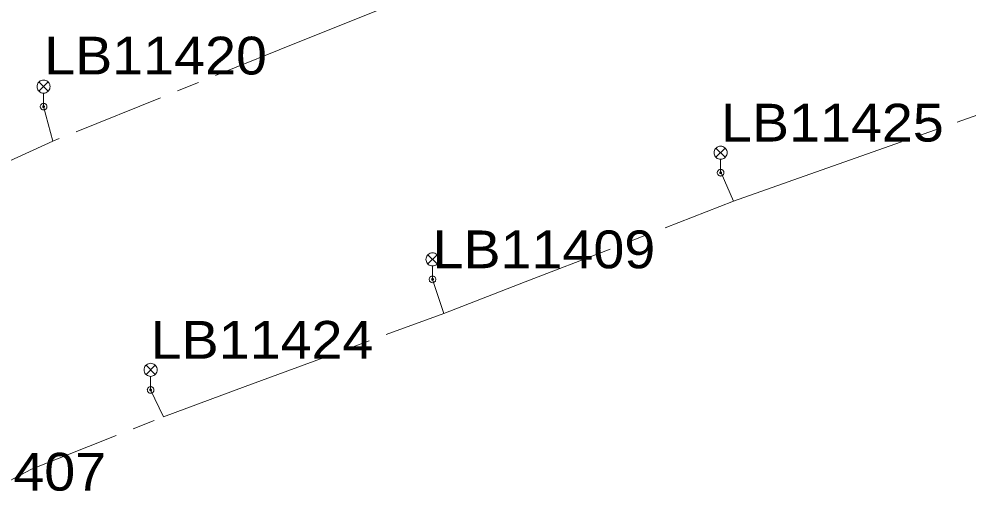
# Model space of a CAD drawing. Extents: x -688049 to -687261, y -973611 to -973038.
# Drawn here: x -687815.7 to -687761.3, y -973356.2 to -973328.5 of the extents above; entities that cross this region are included whole.
import ezdxf

# ---------------------------------------------------------------- set-up
doc = ezdxf.new("R2010")
doc.units = 0
doc.header["$LTSCALE"] = 0.87
doc.linetypes.add('LONG_DASH_SHORT_DASH', pattern=[9.9, 6, -1.2, 1.5, -1.2])
doc.layers.add('1', color=7, linetype='Continuous', lineweight=13)

msp = doc.modelspace()

# ---------------------------------------------------------------- linework, layer by layer
at = {"layer": '1', "linetype": 'LONG_DASH_SHORT_DASH'}
for p, q in [((-687799.628, -973329.809), (-687813.8, -973335.52)), ((-687774.78, -973338.97), (-687770.067, -973337.301)), ((-687791.38, -973345.4), (-687786.718, -973343.594)), ((-687807.46, -973351.33), (-687802.769, -973349.6))]:
    msp.add_line(p, q, dxfattribs=at)
at = {"layer": '1'}
for p, q in [((-687814.595, -973332.125), (-687814.065, -973332.655)), ((-687814.595, -973332.655), (-687814.065, -973332.125)), ((-687814.33, -973333.54), (-687814.33, -973332.765)), ((-687775.78, -973335.915), (-687775.25, -973336.445)), ((-687775.78, -973336.445), (-687775.25, -973335.915)), ((-687775.515, -973337.33), (-687775.515, -973336.555)), ((-687792.295, -973342.035), (-687791.765, -973342.565)), ((-687792.295, -973342.565), (-687791.765, -973342.035)), ((-687792.03, -973343.45), (-687792.03, -973342.675)), ((-687808.455, -973348.375), (-687807.925, -973348.905)), ((-687808.455, -973348.905), (-687807.925, -973348.375)), ((-687808.19, -973349.79), (-687808.19, -973349.015))]:
    msp.add_line(p, q, dxfattribs=at)
at = {"layer": '1', "linetype": 'LONG_DASH_SHORT_DASH'}
for points in [[(-687795.64, -973326.32), (-687794.99, -973327.94), (-687799.628, -973329.809)], [(-687770.067, -973337.301), (-687758.4, -973333.17), (-687759.19, -973331.11)], [(-687814.33, -973333.54), (-687813.8, -973335.52), (-687818.35, -973337.594)], [(-687786.718, -973343.594), (-687774.78, -973338.97), (-687775.49, -973337.33)], [(-687802.769, -973349.6), (-687791.38, -973345.4), (-687792.03, -973343.45)], [(-687818.494, -973356.165), (-687815.02, -973354.34), (-687807.46, -973351.33), (-687808.19, -973349.79)]]:
    msp.add_lwpolyline(points, dxfattribs=at)
at = {"layer": '1'}
for points in [[(-687813.955, -973332.39), (-687813.961, -973332.325), (-687813.978, -973332.262), (-687814.005, -973332.202), (-687814.043, -973332.149), (-687814.089, -973332.103), (-687814.142, -973332.065), (-687814.202, -973332.038), (-687814.265, -973332.021), (-687814.33, -973332.015), (-687814.395, -973332.021), (-687814.458, -973332.038), (-687814.518, -973332.065), (-687814.571, -973332.103), (-687814.617, -973332.149), (-687814.655, -973332.202), (-687814.682, -973332.262), (-687814.699, -973332.325), (-687814.705, -973332.39), (-687814.699, -973332.455), (-687814.682, -973332.518), (-687814.655, -973332.578), (-687814.617, -973332.631), (-687814.571, -973332.677), (-687814.518, -973332.715), (-687814.458, -973332.742), (-687814.395, -973332.759), (-687814.33, -973332.765), (-687814.265, -973332.759), (-687814.202, -973332.742), (-687814.142, -973332.715), (-687814.089, -973332.677), (-687814.043, -973332.631), (-687814.005, -973332.578), (-687813.978, -973332.518), (-687813.961, -973332.455)], [(-687814.14, -973333.54), (-687814.143, -973333.507), (-687814.151, -973333.475), (-687814.165, -973333.445), (-687814.184, -973333.418), (-687814.208, -973333.394), (-687814.235, -973333.375), (-687814.265, -973333.361), (-687814.297, -973333.353), (-687814.33, -973333.35), (-687814.363, -973333.353), (-687814.395, -973333.361), (-687814.425, -973333.375), (-687814.452, -973333.394), (-687814.476, -973333.418), (-687814.495, -973333.445), (-687814.509, -973333.475), (-687814.517, -973333.507), (-687814.52, -973333.54), (-687814.517, -973333.573), (-687814.509, -973333.605), (-687814.495, -973333.635), (-687814.476, -973333.662), (-687814.452, -973333.686), (-687814.425, -973333.705), (-687814.395, -973333.719), (-687814.363, -973333.727), (-687814.33, -973333.73), (-687814.297, -973333.727), (-687814.265, -973333.719), (-687814.235, -973333.705), (-687814.208, -973333.686), (-687814.184, -973333.662), (-687814.165, -973333.635), (-687814.151, -973333.605), (-687814.143, -973333.573)], [(-687814.28, -973333.54), (-687814.281, -973333.531), (-687814.283, -973333.523), (-687814.287, -973333.515), (-687814.292, -973333.508), (-687814.298, -973333.502), (-687814.305, -973333.497), (-687814.313, -973333.493), (-687814.321, -973333.491), (-687814.33, -973333.49), (-687814.339, -973333.491), (-687814.347, -973333.493), (-687814.355, -973333.497), (-687814.362, -973333.502), (-687814.368, -973333.508), (-687814.373, -973333.515), (-687814.377, -973333.523), (-687814.379, -973333.531), (-687814.38, -973333.54), (-687814.379, -973333.549), (-687814.377, -973333.557), (-687814.373, -973333.565), (-687814.368, -973333.572), (-687814.362, -973333.578), (-687814.355, -973333.583), (-687814.347, -973333.587), (-687814.339, -973333.589), (-687814.33, -973333.59), (-687814.321, -973333.589), (-687814.313, -973333.587), (-687814.305, -973333.583), (-687814.298, -973333.578), (-687814.292, -973333.572), (-687814.287, -973333.565), (-687814.283, -973333.557), (-687814.281, -973333.549)], [(-687775.14, -973336.18), (-687775.146, -973336.115), (-687775.163, -973336.052), (-687775.19, -973335.992), (-687775.228, -973335.939), (-687775.274, -973335.893), (-687775.328, -973335.855), (-687775.387, -973335.828), (-687775.45, -973335.811), (-687775.515, -973335.805), (-687775.58, -973335.811), (-687775.643, -973335.828), (-687775.702, -973335.855), (-687775.756, -973335.893), (-687775.802, -973335.939), (-687775.84, -973335.992), (-687775.867, -973336.052), (-687775.884, -973336.115), (-687775.89, -973336.18), (-687775.884, -973336.245), (-687775.867, -973336.308), (-687775.84, -973336.367), (-687775.802, -973336.421), (-687775.756, -973336.467), (-687775.702, -973336.505), (-687775.643, -973336.532), (-687775.58, -973336.549), (-687775.515, -973336.555), (-687775.45, -973336.549), (-687775.387, -973336.532), (-687775.328, -973336.505), (-687775.274, -973336.467), (-687775.228, -973336.421), (-687775.19, -973336.367), (-687775.163, -973336.308), (-687775.146, -973336.245)], [(-687775.325, -973337.33), (-687775.328, -973337.297), (-687775.336, -973337.265), (-687775.35, -973337.235), (-687775.369, -973337.208), (-687775.393, -973337.184), (-687775.42, -973337.165), (-687775.45, -973337.151), (-687775.482, -973337.143), (-687775.515, -973337.14), (-687775.548, -973337.143), (-687775.58, -973337.151), (-687775.61, -973337.165), (-687775.637, -973337.184), (-687775.661, -973337.208), (-687775.68, -973337.235), (-687775.694, -973337.265), (-687775.702, -973337.297), (-687775.705, -973337.33), (-687775.702, -973337.363), (-687775.694, -973337.395), (-687775.68, -973337.425), (-687775.661, -973337.452), (-687775.637, -973337.476), (-687775.61, -973337.495), (-687775.58, -973337.509), (-687775.548, -973337.517), (-687775.515, -973337.52), (-687775.482, -973337.517), (-687775.45, -973337.509), (-687775.42, -973337.495), (-687775.393, -973337.476), (-687775.369, -973337.452), (-687775.35, -973337.425), (-687775.336, -973337.395), (-687775.328, -973337.363)], [(-687775.465, -973337.33), (-687775.466, -973337.321), (-687775.468, -973337.313), (-687775.472, -973337.305), (-687775.477, -973337.298), (-687775.483, -973337.292), (-687775.49, -973337.287), (-687775.498, -973337.283), (-687775.506, -973337.281), (-687775.515, -973337.28), (-687775.524, -973337.281), (-687775.532, -973337.283), (-687775.54, -973337.287), (-687775.547, -973337.292), (-687775.553, -973337.298), (-687775.558, -973337.305), (-687775.562, -973337.313), (-687775.564, -973337.321), (-687775.565, -973337.33), (-687775.564, -973337.339), (-687775.562, -973337.347), (-687775.558, -973337.355), (-687775.553, -973337.362), (-687775.547, -973337.368), (-687775.54, -973337.373), (-687775.532, -973337.377), (-687775.524, -973337.379), (-687775.515, -973337.38), (-687775.506, -973337.379), (-687775.498, -973337.377), (-687775.49, -973337.373), (-687775.483, -973337.368), (-687775.477, -973337.362), (-687775.472, -973337.355), (-687775.468, -973337.347), (-687775.466, -973337.339)], [(-687791.655, -973342.3), (-687791.661, -973342.235), (-687791.678, -973342.172), (-687791.705, -973342.112), (-687791.743, -973342.059), (-687791.789, -973342.013), (-687791.842, -973341.975), (-687791.902, -973341.948), (-687791.965, -973341.931), (-687792.03, -973341.925), (-687792.095, -973341.931), (-687792.158, -973341.948), (-687792.218, -973341.975), (-687792.271, -973342.013), (-687792.317, -973342.059), (-687792.355, -973342.112), (-687792.382, -973342.172), (-687792.399, -973342.235), (-687792.405, -973342.3), (-687792.399, -973342.365), (-687792.382, -973342.428), (-687792.355, -973342.487), (-687792.317, -973342.541), (-687792.271, -973342.587), (-687792.218, -973342.625), (-687792.158, -973342.652), (-687792.095, -973342.669), (-687792.03, -973342.675), (-687791.965, -973342.669), (-687791.902, -973342.652), (-687791.842, -973342.625), (-687791.789, -973342.587), (-687791.743, -973342.541), (-687791.705, -973342.487), (-687791.678, -973342.428), (-687791.661, -973342.365)], [(-687791.84, -973343.45), (-687791.843, -973343.417), (-687791.851, -973343.385), (-687791.865, -973343.355), (-687791.884, -973343.328), (-687791.908, -973343.304), (-687791.935, -973343.285), (-687791.965, -973343.271), (-687791.997, -973343.263), (-687792.03, -973343.26), (-687792.063, -973343.263), (-687792.095, -973343.271), (-687792.125, -973343.285), (-687792.152, -973343.304), (-687792.176, -973343.328), (-687792.195, -973343.355), (-687792.209, -973343.385), (-687792.217, -973343.417), (-687792.22, -973343.45), (-687792.217, -973343.483), (-687792.209, -973343.515), (-687792.195, -973343.545), (-687792.176, -973343.572), (-687792.152, -973343.596), (-687792.125, -973343.615), (-687792.095, -973343.629), (-687792.063, -973343.637), (-687792.03, -973343.64), (-687791.997, -973343.637), (-687791.965, -973343.629), (-687791.935, -973343.615), (-687791.908, -973343.596), (-687791.884, -973343.572), (-687791.865, -973343.545), (-687791.851, -973343.515), (-687791.843, -973343.483)], [(-687791.98, -973343.45), (-687791.981, -973343.441), (-687791.983, -973343.433), (-687791.987, -973343.425), (-687791.992, -973343.418), (-687791.998, -973343.412), (-687792.005, -973343.407), (-687792.013, -973343.403), (-687792.021, -973343.401), (-687792.03, -973343.4), (-687792.039, -973343.401), (-687792.047, -973343.403), (-687792.055, -973343.407), (-687792.062, -973343.412), (-687792.068, -973343.418), (-687792.073, -973343.425), (-687792.077, -973343.433), (-687792.079, -973343.441), (-687792.08, -973343.45), (-687792.079, -973343.459), (-687792.077, -973343.467), (-687792.073, -973343.475), (-687792.068, -973343.482), (-687792.062, -973343.488), (-687792.055, -973343.493), (-687792.047, -973343.497), (-687792.039, -973343.499), (-687792.03, -973343.5), (-687792.021, -973343.499), (-687792.013, -973343.497), (-687792.005, -973343.493), (-687791.998, -973343.488), (-687791.992, -973343.482), (-687791.987, -973343.475), (-687791.983, -973343.467), (-687791.981, -973343.459)], [(-687807.815, -973348.64), (-687807.821, -973348.575), (-687807.838, -973348.512), (-687807.865, -973348.452), (-687807.903, -973348.399), (-687807.949, -973348.353), (-687808.003, -973348.315), (-687808.062, -973348.288), (-687808.125, -973348.271), (-687808.19, -973348.265), (-687808.255, -973348.271), (-687808.318, -973348.288), (-687808.378, -973348.315), (-687808.431, -973348.353), (-687808.477, -973348.399), (-687808.515, -973348.452), (-687808.542, -973348.512), (-687808.559, -973348.575), (-687808.565, -973348.64), (-687808.559, -973348.705), (-687808.542, -973348.768), (-687808.515, -973348.828), (-687808.477, -973348.881), (-687808.431, -973348.927), (-687808.378, -973348.965), (-687808.318, -973348.992), (-687808.255, -973349.009), (-687808.19, -973349.015), (-687808.125, -973349.009), (-687808.062, -973348.992), (-687808.003, -973348.965), (-687807.949, -973348.927), (-687807.903, -973348.881), (-687807.865, -973348.828), (-687807.838, -973348.768), (-687807.821, -973348.705)], [(-687808, -973349.79), (-687808.003, -973349.757), (-687808.011, -973349.725), (-687808.025, -973349.695), (-687808.044, -973349.668), (-687808.068, -973349.644), (-687808.095, -973349.625), (-687808.125, -973349.611), (-687808.157, -973349.603), (-687808.19, -973349.6), (-687808.223, -973349.603), (-687808.255, -973349.611), (-687808.285, -973349.625), (-687808.312, -973349.644), (-687808.336, -973349.668), (-687808.355, -973349.695), (-687808.369, -973349.725), (-687808.377, -973349.757), (-687808.38, -973349.79), (-687808.377, -973349.823), (-687808.369, -973349.855), (-687808.355, -973349.885), (-687808.336, -973349.912), (-687808.312, -973349.936), (-687808.285, -973349.955), (-687808.255, -973349.969), (-687808.223, -973349.977), (-687808.19, -973349.98), (-687808.157, -973349.977), (-687808.125, -973349.969), (-687808.095, -973349.955), (-687808.068, -973349.936), (-687808.044, -973349.912), (-687808.025, -973349.885), (-687808.011, -973349.855), (-687808.003, -973349.823)], [(-687808.14, -973349.79), (-687808.141, -973349.781), (-687808.143, -973349.773), (-687808.147, -973349.765), (-687808.152, -973349.758), (-687808.158, -973349.752), (-687808.165, -973349.747), (-687808.173, -973349.743), (-687808.181, -973349.741), (-687808.19, -973349.74), (-687808.199, -973349.741), (-687808.207, -973349.743), (-687808.215, -973349.747), (-687808.222, -973349.752), (-687808.228, -973349.758), (-687808.233, -973349.765), (-687808.237, -973349.773), (-687808.239, -973349.781), (-687808.24, -973349.79), (-687808.239, -973349.799), (-687808.237, -973349.807), (-687808.233, -973349.815), (-687808.228, -973349.822), (-687808.222, -973349.828), (-687808.215, -973349.833), (-687808.207, -973349.837), (-687808.199, -973349.839), (-687808.19, -973349.84), (-687808.181, -973349.839), (-687808.173, -973349.837), (-687808.165, -973349.833), (-687808.158, -973349.828), (-687808.152, -973349.822), (-687808.147, -973349.815), (-687808.143, -973349.807), (-687808.141, -973349.799)]]:
    msp.add_lwpolyline(points, close=True, dxfattribs=at)

# ---------------------------------------------------------------- texts
at = {"layer": '1', "width": 1.1}
for s, p in [('LB11420', (-687814.292, -973331.695)), ('LB11425', (-687775.49, -973335.542)), ('LB11409', (-687792.03, -973342.812)), ('LB11424', (-687808.19, -973348.002)), ('LB11407', (-687823.51, -973355.568))]:
    msp.add_text(s, height=2.168, dxfattribs=at).set_placement(p)

doc.saveas('drawing.dxf')
